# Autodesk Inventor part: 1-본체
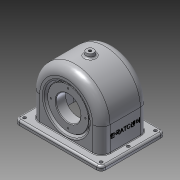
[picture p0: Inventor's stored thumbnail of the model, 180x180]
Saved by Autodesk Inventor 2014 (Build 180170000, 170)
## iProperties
Created: 2015-09
Part Number: 1-본체
Material: 알루미늄 6061
Document SubType Name: Modeling
Designer: Administrator
Density: 2.71 g/cm^3
Appearance: 알루미늄 - 평지
Mass: 722.147 g
Surface Area: 892.287 cm^2
Volume: 266.475 cm^3
Author: Administrator
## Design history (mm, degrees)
sketch "스케치1"
  geometry: L1 (57, 0)-(57, -47); L2 (-57, 0)-(-57, -47); L3 (-57, -47)-(57, -47); A1 r 57 centre (0, 0) between (32.249, -47) and (-32.249, -47); 1 further point
  constraints: 6 end point, 4 point on circle, 2 point on line, 2 tangent, 1 centre point, 1 coincident, 1 perpendicular, 1 vertical
  dimensions: "d1" = 57 radius of A1; "d2" = 47 distance from line of point (0, 0) L3; "d3" = 114 distance of L2.end L1.end
extrude "돌출1" new body sketch "스케치1" stored distance "d4" = 77; taper "d5" = 0 deg
sketch "스케치3"
  geometry: L1 (127, 13.5)-(-13, 13.5); L2 (-13, 13.5)-(-13, -90.5); L3 (-13, -90.5)-(127, -90.5); L4 (127, -90.5)-(127, 13.5); L5 (114, 0)-(0, 0) reference; L6 (114, 0)-(114, -77) reference; 4 further points
  constraints: 8 end point, 3 midpoint, 2 parallel, 1 horizontal, 1 horizontal alignment, 1 perpendicular, 1 vertical alignment
  dimensions: "d8" = 104 distance of L3.end L1.start; "d9" = 140 distance of L1.start L1.end
extrude "돌출2" join sketch "스케치3" distance "d11" = 7; taper "d12" = 0 deg
fillet "모깎기1" dims "d13" = 14
fillet "모깎기2" dims "d14" = 7
sketch "스케치5"
  geometry: L1 (57, -40)-(57, 0) reference; L2 (-57, 0)-(-57, -40) reference; L3 (-51, -47)-(-51, 0); L4 (51, 0)-(51, -47); L5 (63, -47)-(-63, -47) reference; A1 r 57 centre (0, 0) between (57, 0) and (-57, 0) reference; A2 r 51 centre (0, 0) between (51, 0) and (-51, 0); 1 further point
  constraints: 4 end point, 2 point on circle, 2 point on line, 1 centre point, 2 other
  dimensions: "d16" = 6 radial gap between concentric circles of A1 A2
extrude "돌출3" cut sketch "스케치5" stored distance "d17" = 67; taper "d18" = 0 deg
fillet "모깎기3" dims "d19" = 9
node "작업 평면1"
sketch "스케치6"
  geometry: C1 r 6 at (63, 52); 1 further point
  constraints: 1 centre point, 1 coincident
  dimensions: "d21" = 12 diameter of C1
extrude "돌출4" join sketch "스케치6" stored distance "d22" = 67; taper "d23" = 10 deg
sketch "스케치7"
  geometry: L1 (-33.5, 39.747)-(-19.5, 28); L2 (-19.5, 28)-(-19.5, 0); L3 (-33.5, 39.747)-(-33.5, 0); L4 (-33.5, 42)-(-33.5, 0) reference; L5 (24.5, 0)-(-24.5, 0) reference; L6 (-38.5, 0)-(-38.5, 43) reference; L7 (-19.5, 0)-(-33.5, 0); 1 further point
  constraints: 8 end point, 3 point on line, 1 collinear, 1 parallel, 1 vertical
  dimensions: "d24" = 28 distance from line of L5 L1.end; "d25" = 50 deg angle of L1 L2; "d26" = 19 distance between parallel lines of L2 L6
revolve "회전1" sketch "스케치7" stored, may be unused: angle "d27" = 90 deg
sketch "스케치8"
  geometry: C1 r 31 at (0, 0); 1 further point
  constraints: 1 centre point, 1 coincident
  dimensions: "d29" = 62 diameter of C1
extrude "돌출5" join sketch "스케치8" distance "d30" = 10; taper "d31" = 0 deg
sketch "스케치9"
  geometry: L1 (-38.5, 37.416)-(-33.237, 33); L2 (-33.237, 33)-(-35.5, 33); L3 (-35.5, 33)-(-35.5, 0); L4 (-38.5, 37.416)-(-38.5, 0); L5 (-38.5, 0)-(-35.5, 0); L6 (-33.5, 39.747)-(-19.5, 28) reference; 2 further points
  constraints: 10 end point, 2 parallel, 2 perpendicular, 1 coincident, 1 horizontal
  dimensions: "d32" = 3 distance between parallel lines of L3 L4; "d33" = 33 distance from line of point (0, 0) L2; "d34" = 5 distance between parallel lines of L6 L1
revolve "회전2" sketch "스케치9" stored, may be unused: angle "d35" = 90 deg
hole "구멍1" diameter "d38" = 40; stored, may be unused: countersink angle "d42" = 90 deg, drill point angle "d44" = 118 deg; dims "d36" = 10, "d37" = 10, "d39" = 6, "d40" = 4, "d41" = 2, "d43" = 8
chamfer "모따기1" distance "d45" = 1; stored, may be unused: second distance "d46" = 2, angle "d47" = 45 deg
fillet "모깎기4" dims "d48" = 1
hole "구멍2" diameter "d51" = 4.459; stored, may be unused: countersink angle "d55" = 90 deg, drill point angle "d57" = 118 deg; dims "d52" = 50, "d53" = 4, "d54" = 2, "d56" = 8, "d58" = 10, "d59" = 10
fillet "모깎기5" dims "d60" = 3
sketch "스케치10"
  geometry: L1 (0, 0)-(0, -24)
  constraints: 2 end point, 1 vertical
  dimensions: "d61" = 24 distance of L1.start L1.end
hole "구멍3" sketch "스케치10" at (0, -24) diameter "d62" = 2.459; stored, may be unused: countersink angle "d66" = 90 deg, drill point angle "d68" = 118 deg; dims "d63" = 6, "d64" = 4, "d65" = 2, "d67" = 8
sketch "스케치11"
  geometry: L1 (0, 0)-(0, 28)
  constraints: 2 end point, 1 vertical
  dimensions: "d72" = 28 distance of L1.start L1.end
hole "구멍4" sketch "스케치11" at (0, 28) diameter "d73" = 2.459; stored, may be unused: countersink angle "d77" = 90 deg, drill point angle "d79" = 118 deg; dims "d74" = 7, "d75" = 4, "d76" = 2, "d78" = 9
fillet "모깎기6" dims "d83" = 0.5
fillet "모깎기7" dims "d84" = 3
sketch "스케치12"
  geometry: L1 (-119, -82.5)-(5, -82.5); L2 (5, -82.5)-(5, 5.5); L3 (5, 5.5)-(-119, 5.5); L4 (-119, 5.5)-(-119, -82.5); L5 (-127, -83.5)-(-127, 6.5) reference; L6 (-120, -90.5)-(6, -90.5) reference; 3 further points
  constraints: 8 end point, 2 midpoint, 2 parallel, 1 horizontal, 1 horizontal alignment, 1 perpendicular, 1 vertical alignment
  dimensions: "d102" = 8 distance between parallel lines of L5 L4; "d103" = 8 distance between parallel lines of L6 L1
sketch "스케치13"
  geometry: L1 (6.276, -0.387)-(6.276, 49.387); L2 (6.276, 49.387)-(27.724, 49.387); L3 (27.724, 49.387)-(27.724, -0.387); L4 (27.724, -0.387)-(6.276, -0.387); L5 (47, 69.5)-(47, -20.5) reference; L6 (0, -14)-(39, -14) reference; 3 further points
  constraints: 2 midpoint, 2 other
  dimensions: "d98" = 30 distance from line of L5 point (17, -0.387); "d99" = 38.5 distance from line of L6 point (6.276, 24.5)
feature "엠보싱1" sketch "스케치13" dims "d1" = 57, "d2" = 47, "d3" = 114, "d100" = 0.5, "d101" = 0
hole "구멍6" sketch "스케치12" diameter "d104" = 5; stored, may be unused: countersink angle "d108" = 90 deg, drill point angle "d110" = 118 deg; dims "d105" = 6, "d106" = 4, "d107" = 2, "d109" = 8
node "솔리드1"
pattern_circular "원형 패턴1" dims angle "d70" = 360 deg
pattern_circular "원형 패턴2" dims angle "d81" = 360 deg
pattern_linear "직사각형 패턴2" dims "d113" = 44, "d116" = 124
